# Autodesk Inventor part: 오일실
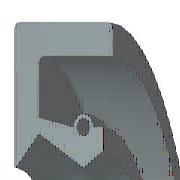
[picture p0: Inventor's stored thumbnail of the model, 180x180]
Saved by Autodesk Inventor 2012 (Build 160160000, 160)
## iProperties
Created: 2014-07
Part Number: 오일실
Material: 고무
Description: 오일-실
Document SubType Name: Modeling
Standard: KS B 2804
Designer: KYOUNG IL JANG
Standards Organization: KS
Language: ko-KR
Size Designation: D - 10 20 7
Categories: <MemberInstance><Categories><Category DisplayName="샤프트 부품" InternalName="7f7aeb1f-a693-4053-b835-cee3144e0d98" Mnemonic="SHFT"><Category DisplayName="실링" Intern
Density: 0.93 g/cm^3
Mass: 1.11329 g
Surface Area: 16.3871 cm^2
Volume: 1.19708 cm^3
Company: 한국ATC센터
IsCustomPart: 0
Author: KYOUNG IL JANG
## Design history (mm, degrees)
revolve "본체" stored, may be unused: angle "d17" = 90 deg
revolve "스프링1" stored, may be unused: angle "d18" = 90 deg
body "Solid1"
sketch "스케치1"
  geometry: L1 (0, 10)-(7, 10); L2 (7, 8.25)-(1.75, 8.25); L3 (1.75, 6.75)-(4.9, 5); L4 (4.9, 5)-(0, 5); L5 (0, 0)-(9.586, 0) reference; L6 (4.9, 5)-(6.3, 5.875); L7 (0, 18)-(0, -3) reference; L8 (-1.941, 0)-(11.507, 0) reference; L9 (4.2, 7.1)-(1.75, 7.59); L10 (1.75, 7.59)-(1.75, 8.25); L11 (0, 10)-(0, 5.088); L12 (4.9, 5)-(0, 5); L13 (1.75, 6.75)-(0.152, 5.028); L14 (7, 10)-(7, 8.25); L15 (5.6, 7.1)-(6.3, 7.1); L16 (6.3, 7.1)-(6.3, 5.875); C1 r 0.455 at (4.9, 7.1); A1 r 0.7 centre (4.9, 7.1) between (5.6, 7.1) and (4.2, 7.1); A2 r 0.088 centre (0.088, 5.088) between (0, 5.088) and (0.152, 5.028); 1 further point
  constraints: 28 end point, 5 horizontal alignment, 5 point on line, 4 point on circle, 4 vertical alignment, 3 centre point, 3 tangent, 2 collinear, 2 horizontal, 2 perpendicular, 1 coincident, 1 parallel
  dimensions: "d0" = 20 diameter of L1 L5 (= SD2); "d1" = 1.75 distance of L1.end L2.start (= SD); "d2" = 0.91 diameter of C1 (= SPDI); "d3" = 1.4 diameter of A1 (= SPDA); "d4" = 10 diameter of L3.end L5 (= NND); "d5" = 13.5 diameter of L3.start L5 (= TKDM); "d7" = 15.18 diameter of L9.end L5 (= TKDM + 0.24 x SWDT); "d8" = 1.75 distance between parallel lines of L11 L10 (= SD); "d9" = 4.9 distance from line of L11 C1.centre (= SPDST); "d10" = 14.2 diameter of C1.centre L5 (= HLDM); "d11" = 0.0875 radius of A2 (= 0.25 x LAB); "d12" = 6.3 distance between parallel lines of L11 L16 (= SDI); "d13" = 11.75 diameter of L6.end L5 (= ABDM); "d14" = 7 distance from line of L11 L1.end (= SWDT)
fillet "모깎기1" dims "d6" = 0.3 (= RR)
other parameters: "SD2" = 20 [user parameter; used in 1 equation term], "SWDT" = 7 [user parameter; used in 2 equation terms], "RR" = 0.3 [user parameter; used in 1 equation term], "SD" = 1.75 [user parameter; used in 2 equation terms], "NND" = 10 [user parameter; used in 1 equation term], "SPDA" = 1.4 [user parameter; used in 1 equation term], "SPDI" = 0.91 [user parameter; used in 1 equation term], "TKDM" = 13.5 [user parameter; used in 2 equation terms], "HLDM" = 14.2 [user parameter; used in 1 equation term], "ABDM" = 11.75 [user parameter; used in 1 equation term], "SDI" = 6.3 [user parameter; used in 1 equation term], "SPDST" = 4.9 [user parameter; used in 1 equation term], "LAB" = 0.35 [user parameter; used in 1 equation term], "d15" = 0, "d16" = 0, "d19" = 0
